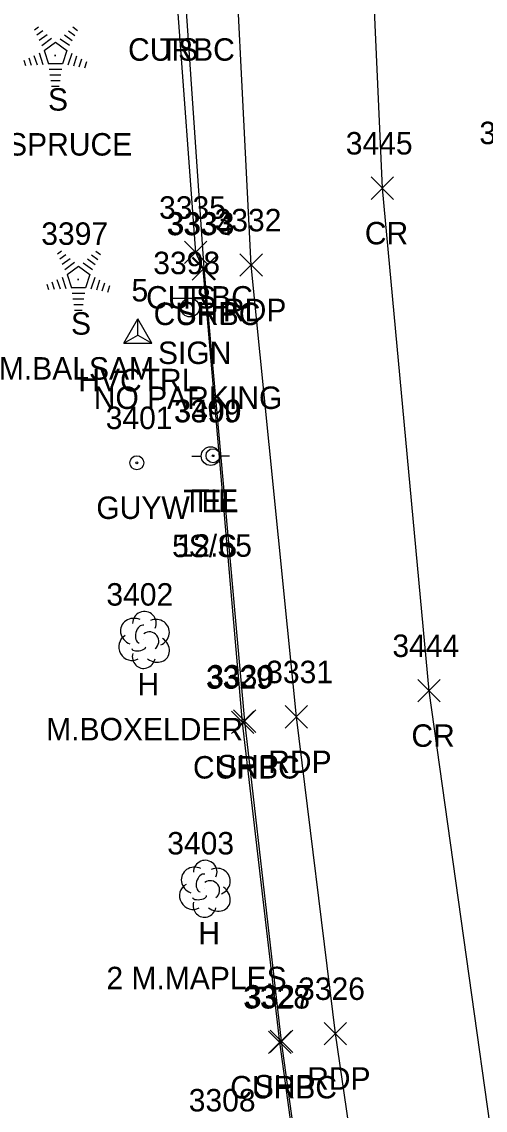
# Model space of a CAD drawing. Extents: x 1769141 to 1770911, y 735471 to 741449.
# Drawn here: x 1770436.6 to 1770477.9, y 737725.5 to 737822.4 of the extents above; entities that cross this region are included whole.
import ezdxf

# ---------------------------------------------------------------- set-up
doc = ezdxf.new("R2010")
doc.units = 0
for name, color, linetype in [('C_A', 7, 'Continuous'), ('C_C', 7, 'Continuous'), ('C_I', 7, 'Continuous'), ('CBP', 7, 'Continuous'), ('CPSM', 7, 'Continuous'), ('L_A', 7, 'Continuous'), ('L_C', 7, 'Continuous'), ('L_I', 7, 'Continuous'), ('L_TIC', 7, 'Continuous'), ('LELB', 7, 'Continuous'), ('LTC', 7, 'Continuous'), ('LTD', 7, 'Continuous'), ('P_A', 7, 'Continuous'), ('P_I', 7, 'Continuous'), ('P_TIC', 7, 'Continuous'), ('PET', 7, 'Continuous'), ('PRC', 7, 'Continuous'), ('PSP', 7, 'Continuous'), ('R_A', 7, 'Continuous'), ('R_I', 7, 'Continuous'), ('R_TIC', 7, 'Continuous'), ('RC', 7, 'Continuous'), ('S_A', 7, 'Continuous'), ('S_C', 7, 'Continuous'), ('S_I', 7, 'Continuous'), ('SSGN', 7, 'Continuous'), ('U_A', 7, 'Continuous'), ('U_C', 7, 'Continuous'), ('U_I', 7, 'Continuous'), ('UP', 7, 'Continuous'), ('UPGW', 7, 'Continuous')]:
    doc.layers.add(name, color=color, linetype=linetype)

msp = doc.modelspace()

# ---------------------------------------------------------------- linework, layer by layer
at = {"layer": 'CBP'}
for radius in [0.625, 0.0833]:
    msp.add_circle((1770453.674, 737783.761), radius, dxfattribs=at)
at = {"layer": 'CPSM'}
for p, q in [((1770445.731, 737793.775), (1770446.981, 737795.94)), ((1770448.231, 737793.775), (1770446.981, 737795.94)), ((1770446.981, 737794.496), (1770446.981, 737795.94)), ((1770445.731, 737793.775), (1770446.981, 737794.496)), ((1770446.981, 737794.496), (1770446.981, 737794.496)), ((1770446.981, 737794.496), (1770448.231, 737793.775)), ((1770445.731, 737793.775), (1770448.231, 737793.775))]:
    msp.add_line(p, q, dxfattribs=at)
at = {"layer": 'L_TIC'}
for points in [[(1770451.132, 737800.859), (1770453.132, 737802.859)], [(1770453.132, 737800.859), (1770451.132, 737802.859)]]:
    msp.add_lwpolyline(points, dxfattribs=at)
at = {"layer": 'LELB'}
msp.add_lwpolyline([(1770452.132, 737801.859), (1770450.525, 737823.927)], dxfattribs=at)
at = {"layer": 'LTC'}
for p, q in [((1770437.787, 737821.691), (1770438.142, 737821.948)), ((1770437.997, 737821.226), (1770438.526, 737821.61)), ((1770440.814, 737821.583), (1770441.364, 737821.184)), ((1770441.186, 737821.931), (1770441.605, 737821.627)), ((1770438.206, 737820.76), (1770438.91, 737821.271)), ((1770438.416, 737820.294), (1770439.294, 737820.932)), ((1770438.641, 737819.839), (1770439.652, 737820.573)), ((1770439.652, 737820.573), (1770440.649, 737819.848)), ((1770440.072, 737820.886), (1770440.882, 737820.298)), ((1770440.443, 737821.235), (1770441.123, 737820.741)), ((1770437.731, 737819.403), (1770438.002, 737818.568)), ((1770438.186, 737819.62), (1770438.517, 737818.601)), ((1770438.641, 737819.839), (1770439.028, 737818.646)), ((1770440.649, 737819.848), (1770440.258, 737818.646)), ((1770441.087, 737819.578), (1770440.749, 737818.538)), ((1770436.82, 737818.97), (1770436.972, 737818.502)), ((1770437.275, 737819.187), (1770437.487, 737818.535)), ((1770440.258, 737818.646), (1770439.028, 737818.646)), ((1770441.531, 737819.327), (1770441.244, 737818.443)), ((1770441.976, 737819.077), (1770441.739, 737818.348)), ((1770442.42, 737818.827), (1770442.233, 737818.253)), ((1770440.22, 737818.146), (1770439.075, 737818.146)), ((1770440.136, 737817.646), (1770439.148, 737817.646)), ((1770440.052, 737817.146), (1770439.221, 737817.146)), ((1770439.968, 737816.646), (1770439.293, 737816.646)), ((1770439.835, 737801.742), (1770440.19, 737802)), ((1770443.233, 737801.983), (1770443.653, 737801.678)), ((1770440.045, 737801.277), (1770440.574, 737801.661)), ((1770440.254, 737800.811), (1770440.958, 737801.322)), ((1770440.464, 737800.345), (1770441.342, 737800.983)), ((1770442.12, 737800.938), (1770442.93, 737800.349)), ((1770442.491, 737801.286), (1770443.171, 737800.792)), ((1770442.862, 737801.634), (1770443.412, 737801.235)), ((1770440.688, 737799.89), (1770441.7, 737800.625)), ((1770441.7, 737800.625), (1770442.697, 737799.9)), ((1770438.868, 737799.021), (1770439.02, 737798.553)), ((1770439.323, 737799.238), (1770439.535, 737798.586)), ((1770439.778, 737799.455), (1770440.05, 737798.619)), ((1770440.234, 737799.671), (1770440.565, 737798.652)), ((1770440.688, 737799.89), (1770441.076, 737798.697)), ((1770442.697, 737799.9), (1770442.306, 737798.697)), ((1770443.135, 737799.629), (1770442.797, 737798.589)), ((1770443.579, 737799.378), (1770443.292, 737798.494)), ((1770444.024, 737799.128), (1770443.787, 737798.399)), ((1770442.306, 737798.697), (1770441.076, 737798.697)), ((1770442.268, 737798.197), (1770441.123, 737798.197)), ((1770444.468, 737798.878), (1770444.281, 737798.304)), ((1770442.184, 737797.697), (1770441.196, 737797.697)), ((1770442.1, 737797.197), (1770441.268, 737797.197)), ((1770442.016, 737796.697), (1770441.341, 737796.697))]:
    msp.add_line(p, q, dxfattribs=at)
at = {"layer": 'LTD'}
for p, q in [((1770447.518, 737767.413), (1770447.518, 737767.413)), ((1770447.518, 737767.413), (1770447.518, 737767.413)), ((1770452.936, 737745.256), (1770452.936, 737745.256)), ((1770452.936, 737745.256), (1770452.936, 737745.256))]:
    msp.add_line(p, q, dxfattribs=at)
for centre in [(1770447.565, 737768.847), (1770452.982, 737746.69)]:
    msp.add_arc(centre, 1.047, 335.52715, 180.95627, dxfattribs=at)
for centre, major_axis, ratio, start_param, end_param in [((1770446.727, 737768.08), (1.21, -0.512), 0.895232, 1.570796, 4.712389), ((1770448.56, 737767.997), (-1.141, -0.483), 0.949671, 1.570796, 4.712389), ((1770447.31, 737767.871), (-0.208, -0.792), 0.645439, 3.141593, 6.283185), ((1770448.018, 737767.247), (-0.5, 0.667), 0.989748, 3.141593, 6.283185), ((1770446.435, 737766.705), (0.584, -1.042), 0.959034, 3.141593, 6.283185), ((1770448.519, 737766.58), (-1.09, 0.792), 0.841452, 1.570796, 4.712389), ((1770447.519, 737765.913), (0.265, 1.061), 0.942809, 1.570796, 4.712389), ((1770447.06, 737766.663), (-0.625, -0.083), 0.423636, 0, 3.141593), ((1770452.144, 737745.923), (1.21, -0.512), 0.895232, 1.570796, 4.712389), ((1770453.977, 737745.84), (-1.141, -0.483), 0.949671, 1.570796, 4.712389), ((1770452.727, 737745.714), (-0.208, -0.792), 0.645439, 3.141593, 6.283185), ((1770453.436, 737745.089), (-0.5, 0.667), 0.989748, 3.141593, 6.283185), ((1770451.852, 737744.547), (0.584, -1.042), 0.959034, 3.141593, 6.283185), ((1770453.936, 737744.423), (-1.09, 0.792), 0.841452, 1.570796, 4.712389), ((1770452.936, 737743.756), (0.265, 1.061), 0.942809, 1.570796, 4.712389), ((1770452.477, 737744.506), (-0.625, -0.083), 0.423636, 0, 3.141593)]:
    msp.add_ellipse(centre, major_axis=major_axis, ratio=ratio, start_param=start_param, end_param=end_param, dxfattribs=at)
at = {"layer": 'P_TIC'}
for points in [[(1770467.758, 737806.576), (1770469.758, 737808.576)], [(1770469.758, 737806.576), (1770467.758, 737808.576)], [(1770451.891, 737799.447), (1770453.891, 737801.447)], [(1770453.891, 737799.447), (1770451.891, 737801.447)], [(1770456.073, 737799.737), (1770458.073, 737801.737)], [(1770458.073, 737799.737), (1770456.073, 737801.737)], [(1770471.907, 737761.84), (1770473.907, 737763.84)], [(1770473.907, 737761.84), (1770471.907, 737763.84)], [(1770460.101, 737759.505), (1770462.101, 737761.505)], [(1770462.101, 737759.505), (1770460.101, 737761.505)], [(1770455.5, 737759.121), (1770457.5, 737761.121)], [(1770457.5, 737759.121), (1770455.5, 737761.121)], [(1770463.567, 737731.305), (1770465.567, 737733.305)], [(1770465.567, 737731.305), (1770463.567, 737733.305)], [(1770458.771, 737730.624), (1770460.771, 737732.624)], [(1770460.771, 737730.624), (1770458.771, 737732.624)]]:
    msp.add_lwpolyline(points, dxfattribs=at)
at = {"layer": 'PET'}
msp.add_lwpolyline([(1770592.485, 737245.879), (1770581.452, 737278.474), (1770564.99, 737326.698), (1770540.847, 737402.849), (1770531.811, 737432.592), (1770518.162, 737480.642), (1770510.533, 737508.767), (1770497.793, 737560.193), (1770489.765, 737595.241), (1770483.996, 737621.997), (1770479.289, 737645.744), (1770471.868, 737685.433), (1770468.18, 737707.708), (1770464.567, 737732.305), (1770461.101, 737760.505), (1770457.073, 737800.737), (1770455.079, 737840.165)], dxfattribs=at)
at = {"layer": 'PRC'}
msp.add_lwpolyline([(1770611.429, 737227.28), (1770596.591, 737271.455), (1770580.67, 737318.491), (1770564.59, 737367.306), (1770551.927, 737407.862), (1770542.433, 737439.838), (1770534.51, 737467.452), (1770524.198, 737503.427), (1770508.758, 737566.262), (1770499.298, 737611.155), (1770490.313, 737651.948), (1770482.163, 737697.058), (1770472.907, 737762.84), (1770468.758, 737807.576), (1770466.845, 737850.581)], dxfattribs=at)
at = {"layer": 'PSP'}
msp.add_lwpolyline([(1770587.449, 737244.334), (1770575.082, 737276.146), (1770567.835, 737299.318), (1770558.976, 737324.945), (1770547.159, 737358.664), (1770533.811, 737401.321), (1770525.744, 737428.648), (1770525.14, 737430.695), (1770512.342, 737478.307), (1770504.586, 737507.955), (1770491.98, 737559.42), (1770484.109, 737594.151), (1770478.824, 737621.075), (1770474.546, 737643.975), (1770465.86, 737686.481), (1770463.193, 737706.945), (1770459.771, 737731.624), (1770456.5, 737760.121), (1770452.891, 737800.447), (1770450.147, 737840.195)], dxfattribs=at)
at = {"layer": 'R_TIC'}
for points in [[(1770451.132, 737800.859), (1770453.132, 737802.859)], [(1770453.132, 737800.859), (1770451.132, 737802.859)], [(1770451.804, 737799.389), (1770453.804, 737801.389)], [(1770453.804, 737799.389), (1770451.804, 737801.389)], [(1770455.307, 737759.016), (1770457.307, 737761.016)], [(1770457.307, 737759.016), (1770455.307, 737761.016)], [(1770458.62, 737730.536), (1770460.62, 737732.536)], [(1770460.62, 737730.536), (1770458.62, 737732.536)]]:
    msp.add_lwpolyline(points, dxfattribs=at)
at = {"layer": 'RC'}
msp.add_lwpolyline([(1770416.334, 737698.591), (1770417.132, 737697.431), (1770418.612, 737697.087), (1770434.021, 737699.994), (1770455.689, 737703.617), (1770460.652, 737704.431), (1770462.015, 737704.95), (1770462.719, 737705.588), (1770463.019, 737707.013), (1770459.62, 737731.536), (1770456.307, 737760.016), (1770452.804, 737800.389), (1770452.132, 737801.859)], dxfattribs=at)
at = {"layer": 'SSGN'}
for p, q in [((1770449.986, 737797.777), (1770453.319, 737797.777)), ((1770451.633, 737796.944), (1770451.633, 737796.944))]:
    msp.add_line(p, q, dxfattribs=at)
msp.add_circle((1770451.633, 737796.944), 0.833, dxfattribs=at)
at = {"layer": 'UP'}
for p, q in [((1770451.801, 737783.72), (1770452.627, 737783.72)), ((1770453.46, 737783.726), (1770453.46, 737783.726)), ((1770455.127, 737783.726), (1770454.293, 737783.726)), ((1770454.293, 737783.726), (1770454.293, 737783.726)), ((1770455.127, 737783.726), (1770455.127, 737783.726))]:
    msp.add_line(p, q, dxfattribs=at)
msp.add_circle((1770453.46, 737783.726), 0.833, dxfattribs=at)
at = {"layer": 'UPGW'}
for radius in [0.625, 0.0833]:
    msp.add_circle((1770446.891, 737783.129), radius, dxfattribs=at)

# ---------------------------------------------------------------- texts
at = {"layer": 'C_A'}
for s, p in [('HVCTRL', (1770441.674, 737789.496)), ('TIE', (1770451.752, 737778.761))]:
    msp.add_text(s, height=2, dxfattribs=at).set_placement(p)
at = {"layer": 'C_C'}
msp.add_text('12.65', height=2, dxfattribs=at).set_placement((1770450.445, 737774.761))
at = {"layer": 'C_I'}
for s, p in [('5', (1770446.414, 737797.496)), ('3400', (1770450.248, 737786.761))]:
    msp.add_text(s, height=2, dxfattribs=at).set_placement(p)
at = {"layer": 'L_A'}
for s, p in [('TS', (1770448.934, 737818.927)), ('S', (1770438.978, 737814.483)), ('TS', (1770450.541, 737796.859)), ('S', (1770441.026, 737794.534)), ('H', (1770446.951, 737762.413)), ('H', (1770452.369, 737740.256))]:
    msp.add_text(s, height=2, dxfattribs=at).set_placement(p)
at = {"layer": 'L_C'}
for s, p in [('S.SPRUCE', (1770432.805, 737810.483)), ('M.BALSAM', (1770434.601, 737790.534)), ('M.BOXELDER', (1770438.818, 737758.413)), ('2 M.MAPLES', (1770444.18, 737736.256))]:
    msp.add_text(s, height=2, dxfattribs=at).set_placement(p)
at = {"layer": 'L_I'}
for s, p in [('3335', (1770448.872, 737804.859)), ('3397', (1770438.38, 737802.534)), ('3402', (1770444.18, 737770.413)), ('3403', (1770449.597, 737748.256)), ('3308', (1770451.514, 737725.377))]:
    msp.add_text(s, height=2, dxfattribs=at).set_placement(p)
at = {"layer": 'LTC'}
for p in [(1770439.535, 737819.587), (1770441.583, 737799.638)]:
    msp.add_text('.', height=1.037, rotation=270, dxfattribs=at).set_placement(p)
at = {"layer": 'P_A'}
for s, p in [('CR', (1770467.191, 737802.576)), ('SHP', (1770450.426, 737795.447)), ('RDP', (1770454.562, 737795.737)), ('CR', (1770471.34, 737757.84)), ('RDP', (1770458.589, 737755.505)), ('SHP', (1770454.036, 737755.121)), ('RDP', (1770462.056, 737727.305)), ('SHP', (1770457.306, 737726.624))]:
    msp.add_text(s, height=2, dxfattribs=at).set_placement(p)
at = {"layer": 'P_I'}
for s, p in [('3446', (1770477.394, 737811.5)), ('3445', (1770465.498, 737810.576)), ('3333', (1770449.631, 737803.447)), ('3332', (1770453.814, 737803.737)), ('3444', (1770469.647, 737765.84)), ('3330', (1770453.154, 737763.121)), ('3331', (1770458.408, 737763.505)), ('3326', (1770461.252, 737735.305)), ('3327', (1770456.511, 737734.624))]:
    msp.add_text(s, height=2, dxfattribs=at).set_placement(p)
at = {"layer": 'R_A'}
for p in [(1770446.107, 737818.927), (1770447.715, 737796.859), (1770448.386, 737795.389), (1770451.89, 737755.016), (1770455.203, 737726.536)]:
    msp.add_text('CURBC', height=2, dxfattribs=at).set_placement(p)
at = {"layer": 'R_I'}
for s, p in [('3335', (1770448.872, 737804.859)), ('3334', (1770449.544, 737803.389)), ('3329', (1770453.04, 737763.016)), ('3328', (1770456.361, 737734.536))]:
    msp.add_text(s, height=2, dxfattribs=at).set_placement(p)
at = {"layer": 'S_A'}
msp.add_text('SIGN', height=2, dxfattribs=at).set_placement((1770448.771, 737791.923))
at = {"layer": 'S_C'}
msp.add_text('NO PARKING', height=2, dxfattribs=at).set_placement((1770443.054, 737787.923))
at = {"layer": 'S_I'}
msp.add_text('3398', height=2, dxfattribs=at).set_placement((1770448.353, 737799.923))
at = {"layer": 'U_A'}
for s, p in [('TEL', (1770451.019, 737778.726)), ('GUYW', (1770443.284, 737778.129))]:
    msp.add_text(s, height=2, dxfattribs=at).set_placement(p)
at = {"layer": 'U_C'}
msp.add_text('5S/S', height=2, dxfattribs=at).set_placement((1770450.027, 737774.726))
at = {"layer": 'U_I'}
for s, p in [('3399', (1770450.192, 737786.726)), ('3401', (1770444.119, 737786.129))]:
    msp.add_text(s, height=2, dxfattribs=at).set_placement(p)

doc.saveas('drawing.dxf')
